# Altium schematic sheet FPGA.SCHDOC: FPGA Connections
size A2; Organization: Altium Limited.; Address1: Level 3, 12a Rodborough Rd; Address2: Frenchs Forest 2086; Address3: NSW; Address4: AUSTRALIA; DocumentNumber: 3; SheetNumber: 4; SheetTotal: 23; PageSetup: Record=PageOptions|CenterHorizontal=True|CenterVertical=True|PrintScale=0.71|XCorrection=1.00|YCorrection=1.00|PrintKind=0|BorderSize=5000000|LeftOffset=0|BottomOffset=0|Orientation=2|PaperLength=4199|PaperWidth=2969|Scale=100|PaperSource=7|PrintQuality=600|MediaType=1|DitherType=10|PaperKind=A3 (297 x 420 mm)|PrintScaleMode=1
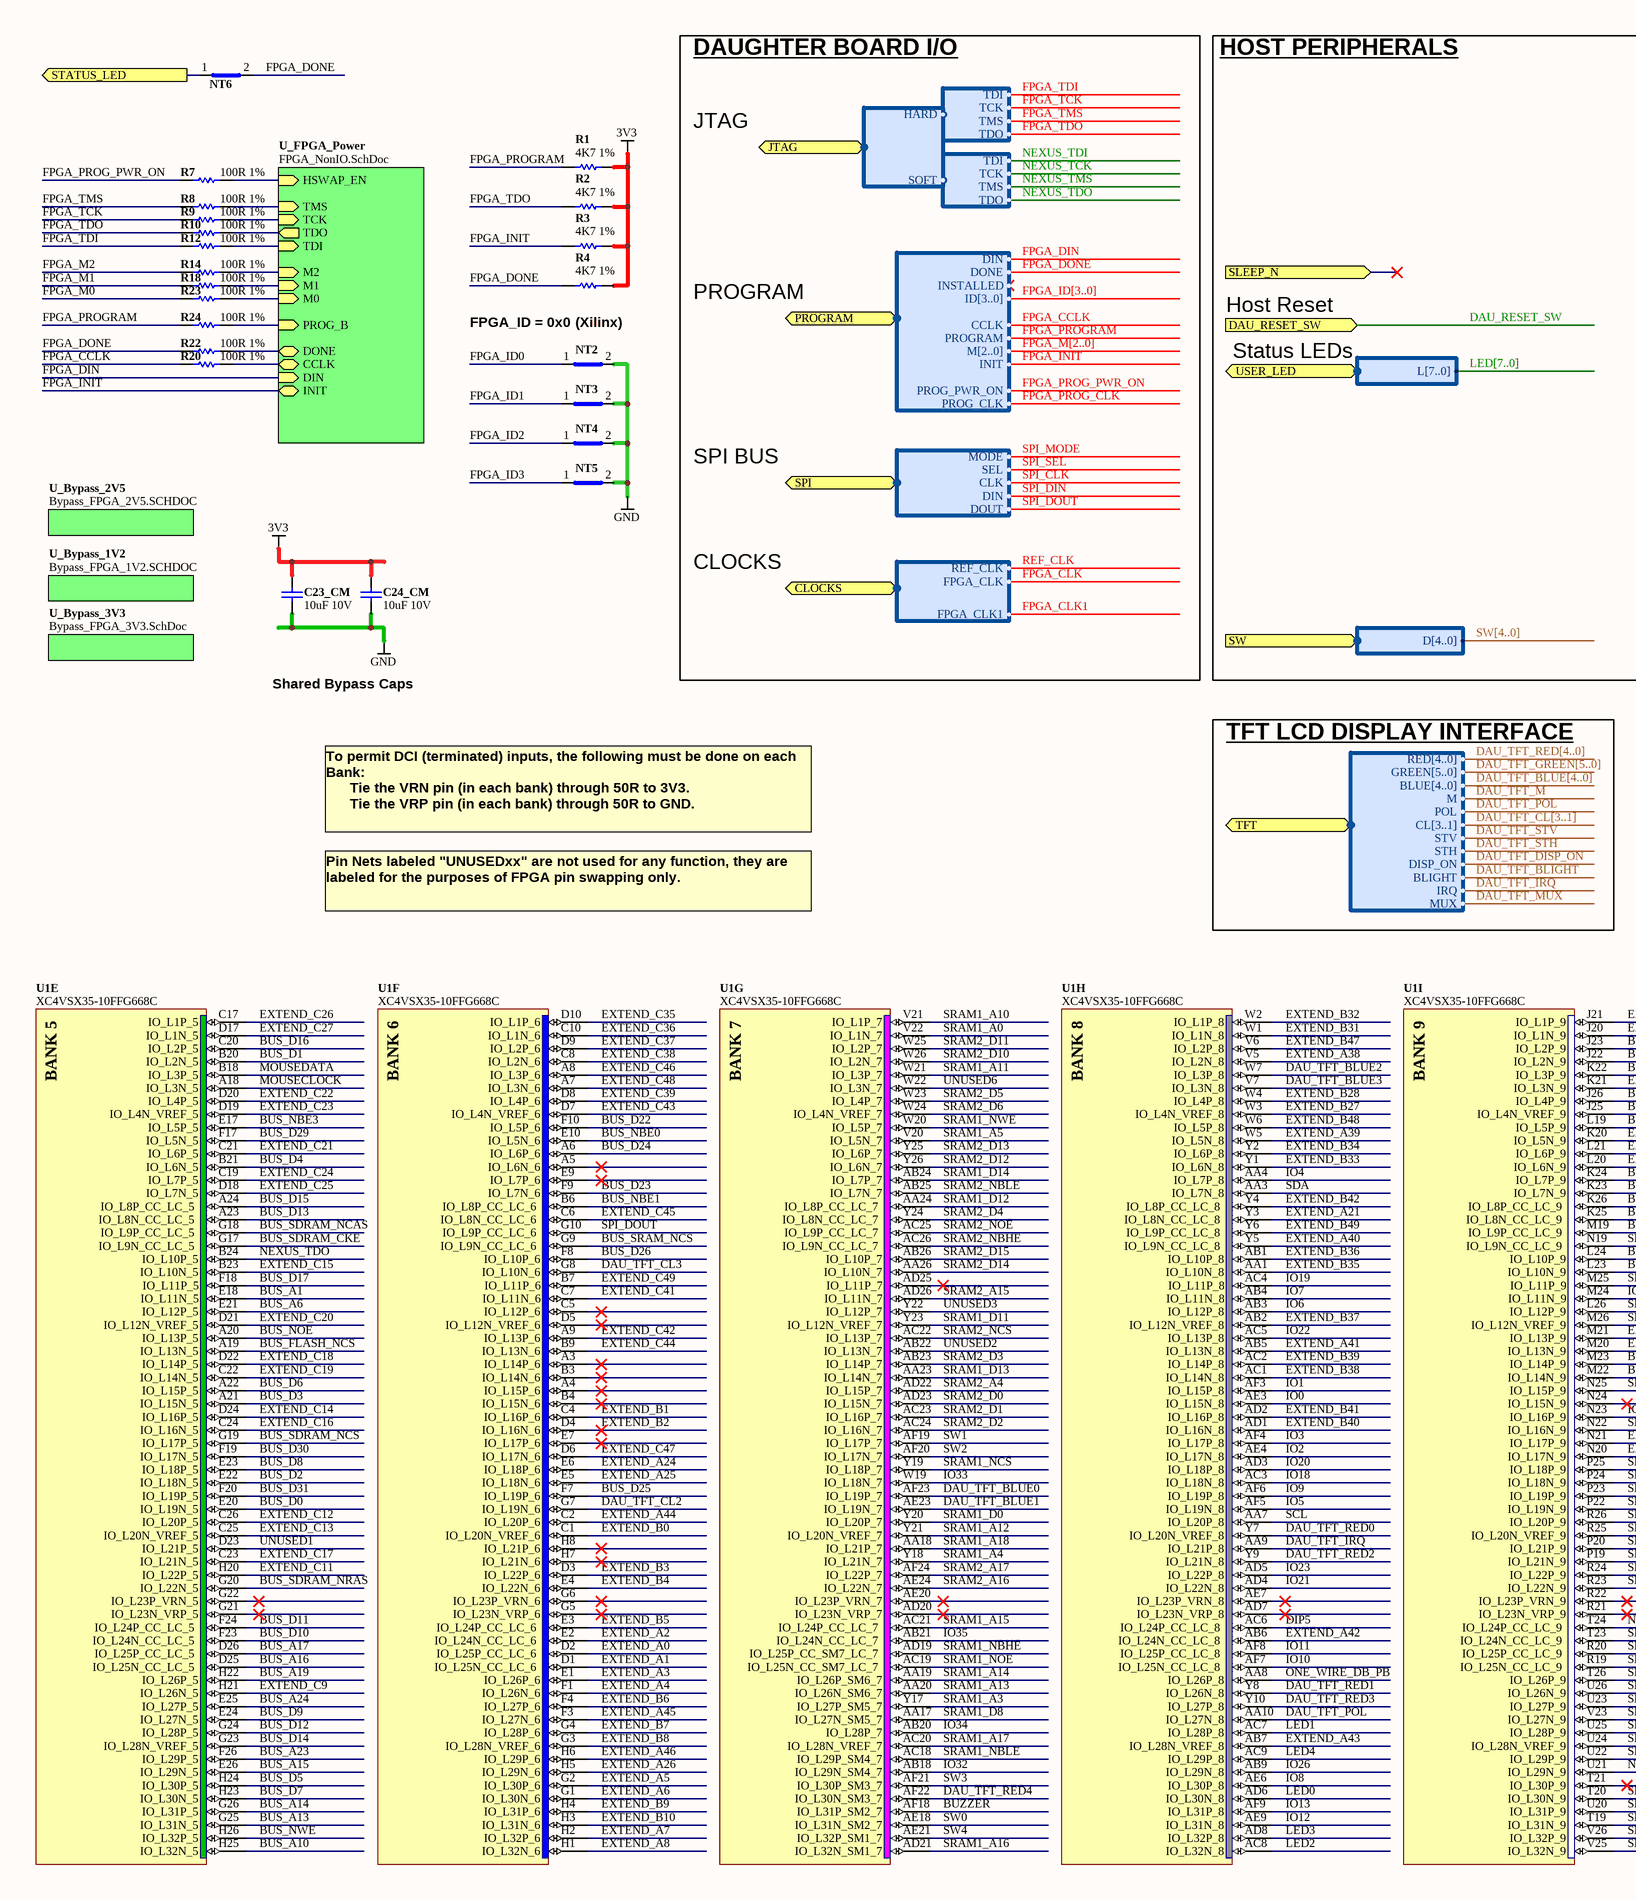
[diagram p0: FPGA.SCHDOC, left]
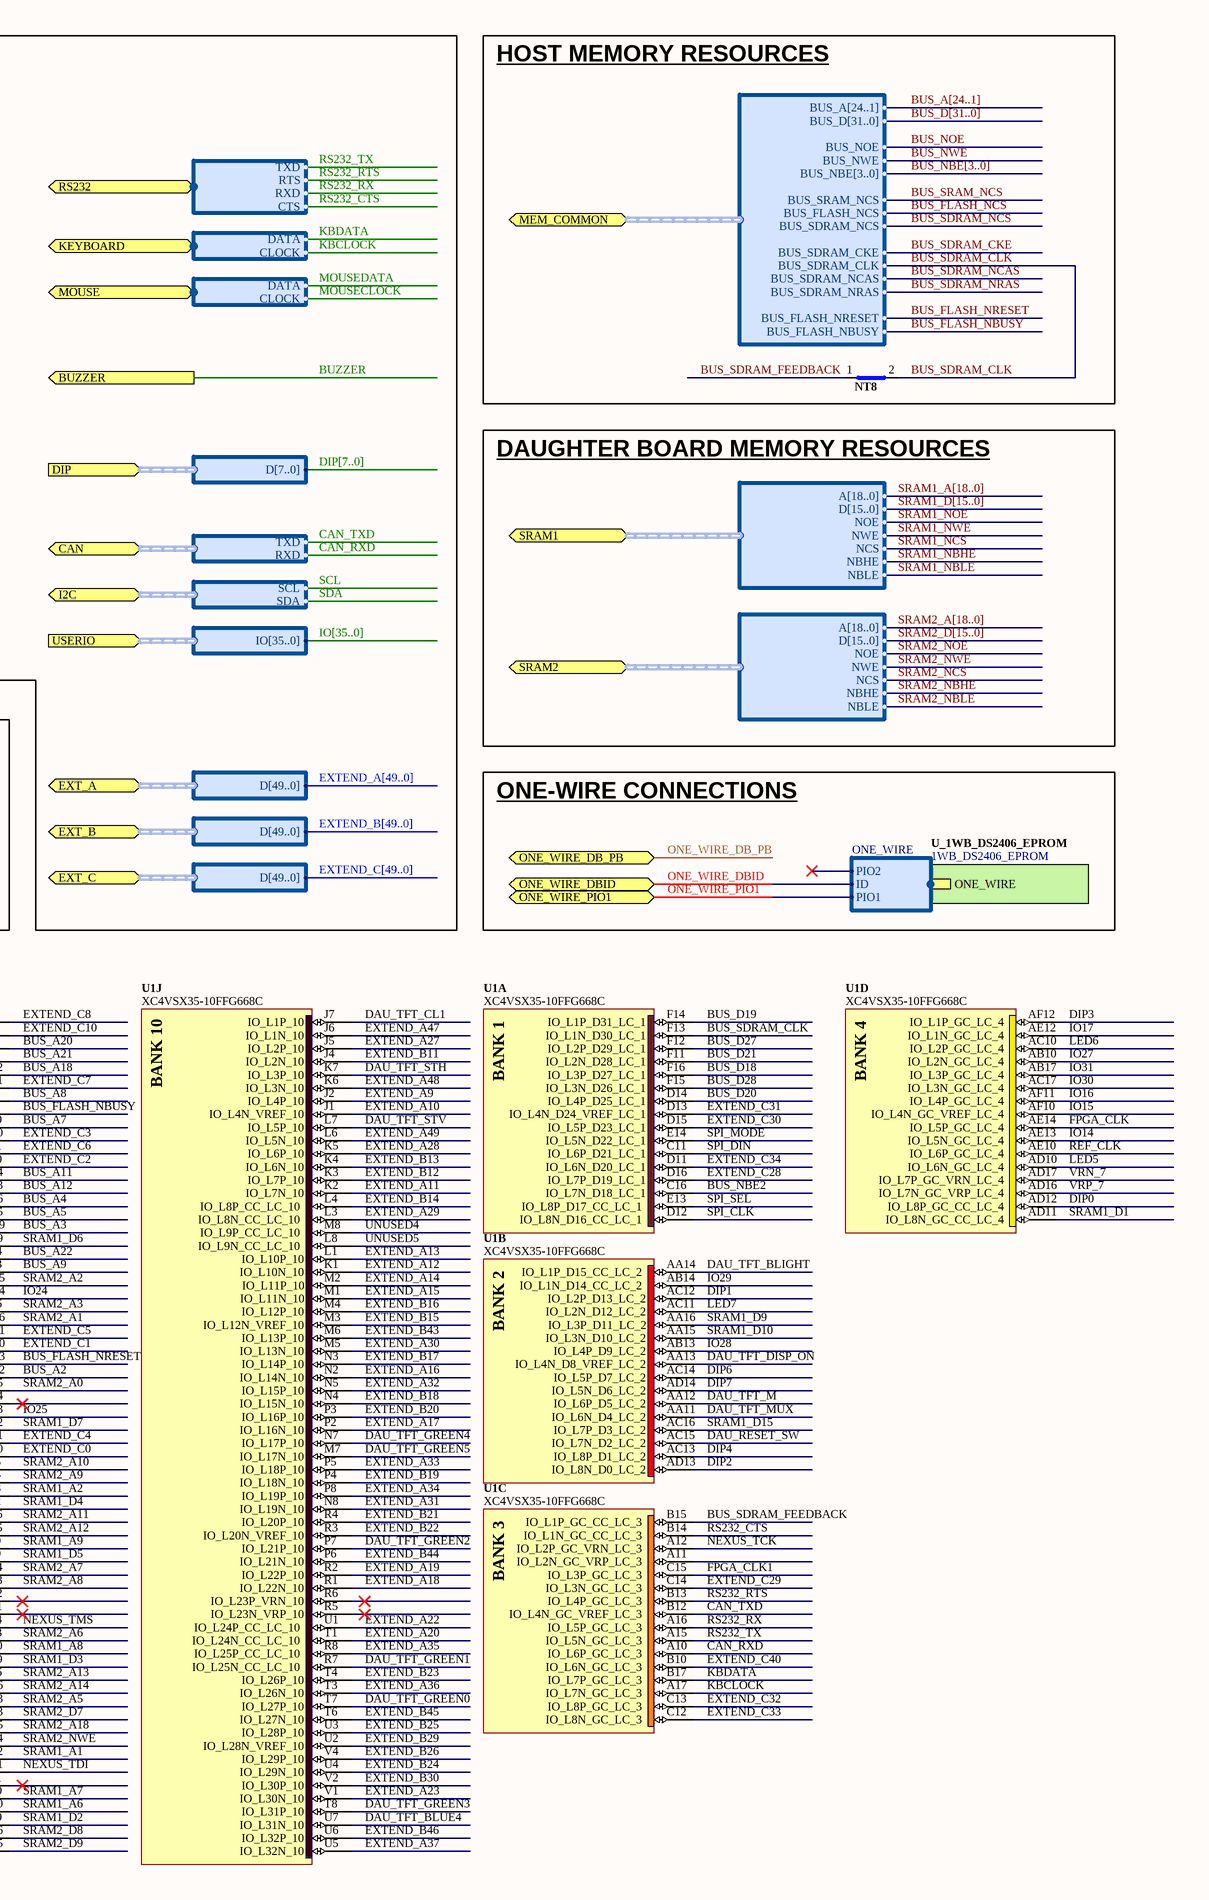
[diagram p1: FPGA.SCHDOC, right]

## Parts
C23_CM  10uF 10V  [CAPC2012-STAR]
C24_CM  10uF 10V  [CAPC2012-STAR]
NT2  Net Tie SMT2  [NETTIE-SMT2-8X8]  (value not drawn)  (net tie, no BOM)
NT3  Net Tie SMT2  [NETTIE-SMT2-8X8]  (value not drawn)  (net tie, no BOM)
NT4  Net Tie SMT2  [NETTIE-SMT2-8X8]  (value not drawn)  (net tie, no BOM)
NT5  Net Tie SMT2  [NETTIE-SMT2-8X8]  (value not drawn)  (net tie, no BOM)
NT6  Net Tie SMT2  [NETTIE-SMT2-8X8]  (value not drawn)  (net tie, no BOM)
NT8  Net Tie SMT2  [NETTIE-SMT2-8X8]  (value not drawn)  (net tie, no BOM)
R1  4K7 1%  [RESC1005-STAR]
R2  4K7 1%  [RESC1005-STAR]
R3  4K7 1%  [RESC1005-STAR]
R4  4K7 1%  [RESC1005-STAR]
R7  100R 1%  [RESC1005-STAR]
R8  100R 1%  [RESC1005-STAR]
R9  100R 1%  [RESC1005-STAR]
R10  100R 1%  [RESC1005-STAR]
R12  100R 1%  [RESC1005-STAR]
R14  100R 1%  [RESC1005-STAR]
R18  100R 1%  [RESC1005-STAR]
R20  100R 1%  [RESC1005-STAR]
R22  100R 1%  [RESC1005-STAR]
R23  100R 1%  [RESC1005-STAR]
R24  100R 1%  [RESC1005-STAR]
U1  XC4VSX35-10FFG668C  [XC4VLX25-10FF668C]  (parts A,B,C,D,E,F,G,H,I,J of 14)

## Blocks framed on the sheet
HOST MEMORY RESOURCES: NT8

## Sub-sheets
U_1WB_DS2406_EPROM = 1WB_DS2406_EPROM: ONE_WIRE (harness ONE_WIRE)
U_Bypass_1V2 = Bypass_FPGA_1V2.SCHDOC: no entries
U_Bypass_2V5 = Bypass_FPGA_2V5.SCHDOC: no entries
U_Bypass_3V3 = Bypass_FPGA_3V3.SchDoc: no entries
U_FPGA_Power = FPGA_NonIO.SchDoc: TMS (in), DONE (bidir), M1 (in), CCLK (bidir), M0 (in), M2 (in), TCK (in), HSWAP_EN (in), TDI (in), PROG_B (in), TDO (out), DIN (in), INIT (bidir)

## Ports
BUZZER (out), CAN (harness CAN_INT), CLOCKS (harness DAU_CLK), DAU_RESET_SW (in), DIP (harness SW8), EXT_A (harness PBIO), EXT_B (harness PBIO), EXT_C (harness PBIO), I2C (harness I2C), JTAG (harness HARDSOFT_JTAG), KEYBOARD (harness PS2), MEM_COMMON (harness HOSTMEMORY), MOUSE (harness PS2), ONE_WIRE_DB_PB (bidir), ONE_WIRE_DBID (bidir), ONE_WIRE_PIO1 (bidir), PROGRAM (harness DAU_CTRL), RS232 (harness RS232_INT), SLEEP_N (in), SPI (harness DAU_SPI), SRAM1 (harness SRAM-256Kx16), SRAM2 (harness SRAM-256Kx16), STATUS_LED (out), SW (harness SW5), TFT (harness DAU_TFT), USER_LED (harness LED8), USERIO (harness IO36)

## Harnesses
ONE_WIRE: ID, PIO1, PIO2
SRAM-256Kx16: A[18..0], D[15..0], NCS, NWE, NOE, NBHE, NBLE
HOSTMEMORY: BUS_A[24..1], BUS_D[31..0], BUS_NOE, BUS_NWE, BUS_NBE[3..0], BUS_SRAM_NCS, BUS_FLASH_NCS, BUS_SDRAM_NCS, BUS_SDRAM_CKE, BUS_SDRAM_CLK, BUS_SDRAM_NCAS, BUS_SDRAM_NRAS, BUS_FLASH_NRESET, BUS_FLASH_NBUSY
DAU_CLK: REF_CLK, FPGA_CLK, FPGA_CLK1
DAU_SPI: MODE, SEL, CLK, DIN, DOUT
DAU_CTRL: DIN, DONE, INSTALLED, ID[3..0], CCLK, PROGRAM, M[2..0], INIT, PROG_PWR_ON, PROG_CLK
JTAG: TMS, TDO, TDI, TCK
HARDSOFT_JTAG: HARD, SOFT
LED8: L[7..0]
SW5: D[4..0]
DAU_TFT: RED[4..0], GREEN[5..0], BLUE[4..0], M, POL, CL[3..1], STV, STH, DISP_ON, BLIGHT, IRQ, MUX
PS2: DATA, CLOCK
RS232_INT: RXD, TXD, RTS, CTS
IO36: IO[35..0]
SW8: D[7..0]
CAN_INT: TXD, RXD
I2C: SCL, SDA
PBIO: D[49..0]

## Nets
3V3: C23_CM.1 C24_CM.1 R1.2 R2.2 R3.2 R4.2
GND: C23_CM.2 C24_CM.2 NT2.2(Net2) NT3.2(Net2) NT4.2(Net2) NT5.2(Net2)
BUS_A1: U1.E18(IO_L11N_5)
BUS_A2: U1.M22(IO_L14N_9)
BUS_A3: U1.M19(IO_L9P_CC_LC_9)
BUS_A4: U1.K26(IO_L8P_CC_LC_9)
BUS_A5: U1.K25(IO_L8N_CC_LC_9)
BUS_A6: U1.E21(IO_L12P_5)
BUS_A7: U1.L19(IO_L5P_9)
BUS_A8: U1.J26(IO_L4P_9)
BUS_A9: U1.L23(IO_L10N_9)
BUS_A10: U1.H25(IO_L32N_5)
BUS_A11: U1.K24(IO_L7P_9)
BUS_A12: U1.K23(IO_L7N_9)
BUS_A13: U1.G25(IO_L31N_5)
BUS_A14: U1.G26(IO_L31P_5)
BUS_A15: U1.E26(IO_L29N_5)
BUS_A16: U1.D25(IO_L25N_CC_LC_5)
BUS_A17: U1.D26(IO_L25P_CC_LC_5)
BUS_A18: U1.K22(IO_L3P_9)
BUS_A19: U1.H22(IO_L26P_5)
BUS_A20: U1.J23(IO_L2P_9)
BUS_A21: U1.J22(IO_L2N_9)
BUS_A22: U1.L24(IO_L10P_9)
BUS_A23: U1.F26(IO_L29P_5)
BUS_A24: U1.E25(IO_L27P_5)
BUS_D0: U1.E20(IO_L19N_5)
BUS_D1: U1.B20(IO_L2N_5)
BUS_D2: U1.E22(IO_L18N_5)
BUS_D3: U1.A21(IO_L15N_5)
BUS_D4: U1.B21(IO_L6N_5)
BUS_D5: U1.H24(IO_L30P_5)
BUS_D6: U1.A22(IO_L15P_5)
BUS_D7: U1.H23(IO_L30N_5)
BUS_D8: U1.E23(IO_L18P_5)
BUS_D9: U1.E24(IO_L27N_5)
BUS_D10: U1.F23(IO_L24N_CC_LC_5)
BUS_D11: U1.F24(IO_L24P_CC_LC_5)
BUS_D12: U1.G24(IO_L28P_5)
BUS_D13: U1.A23(IO_L8N_CC_LC_5)
BUS_D14: U1.G23(IO_L28N_VREF_5)
BUS_D15: U1.A24(IO_L8P_CC_LC_5)
BUS_D16: U1.C20(IO_L2P_5)
BUS_D17: U1.F18(IO_L11P_5)
BUS_D18: U1.F16(IO_L3P_D27_LC_1)
BUS_D19: U1.F14(IO_L1P_D31_LC_1)
BUS_D20: U1.D14(IO_L4P_D25_LC_1)
BUS_D21: U1.F11(IO_L2N_D28_LC_1)
BUS_D22: U1.F10(IO_L5P_6)
BUS_D23: U1.F9(IO_L7N_6)
BUS_D24: U1.A6(IO_L6P_6)
BUS_D25: U1.F7(IO_L19P_6)
BUS_D26: U1.F8(IO_L10P_6)
BUS_D27: U1.F12(IO_L2P_D29_LC_1)
BUS_D28: U1.F15(IO_L3N_D26_LC_1)
BUS_D29: U1.F17(IO_L5N_5)
BUS_D30: U1.F19(IO_L17N_5)
BUS_D31: U1.F20(IO_L19P_5)
BUS_FLASH_NBUSY: U1.J25(IO_L4N_VREF_9) ; port MEM_COMMON.BUS_FLASH_NBUSY
BUS_FLASH_NCS: U1.A19(IO_L13N_5) ; port MEM_COMMON.BUS_FLASH_NCS
BUS_FLASH_NRESET: U1.M23(IO_L14P_9) ; port MEM_COMMON.BUS_FLASH_NRESET
BUS_NBE0: U1.E10(IO_L5N_6)
BUS_NBE1: U1.B6(IO_L8P_CC_LC_6)
BUS_NBE2: U1.C16(IO_L7N_D18_LC_1)
BUS_NBE3: U1.E17(IO_L5P_5)
BUS_NOE: U1.A20(IO_L13P_5) ; port MEM_COMMON.BUS_NOE
BUS_NWE: U1.H26(IO_L32P_5) ; port MEM_COMMON.BUS_NWE
BUS_SDRAM_CKE: U1.G17(IO_L9N_CC_LC_5) ; port MEM_COMMON.BUS_SDRAM_CKE
BUS_SDRAM_CLK: NT8.2(Net2) U1.F13(IO_L1N_D30_LC_1) ; port MEM_COMMON.BUS_SDRAM_CLK
BUS_SDRAM_FEEDBACK: NT8.1(Net1) U1.B15(IO_L1P_GC_CC_LC_3)
BUS_SDRAM_NCAS: U1.G18(IO_L9P_CC_LC_5) ; port MEM_COMMON.BUS_SDRAM_NCAS
BUS_SDRAM_NCS: U1.G19(IO_L17P_5) ; port MEM_COMMON.BUS_SDRAM_NCS
BUS_SDRAM_NRAS: U1.G20(IO_L22N_5) ; port MEM_COMMON.BUS_SDRAM_NRAS
BUS_SRAM_NCS: U1.G9(IO_L9N_CC_LC_6) ; port MEM_COMMON.BUS_SRAM_NCS
BUZZER: U1.AF18(IO_L31P_SM2_7) ; port BUZZER
CAN_RXD: U1.A10(IO_L6P_GC_LC_3) ; port CAN.RXD
CAN_TXD: U1.B12(IO_L4N_GC_VREF_LC_3) ; port CAN.TXD
DAU_RESET_SW: U1.AC15(IO_L7N_D2_LC_2) ; port DAU_RESET_SW
DAU_TFT_BLIGHT: U1.AA14(IO_L1P_D15_CC_LC_2) ; port TFT.BLIGHT
DAU_TFT_BLUE0: U1.AF23(IO_L19P_7)
DAU_TFT_BLUE1: U1.AE23(IO_L19N_7)
DAU_TFT_BLUE2: U1.W7(IO_L3P_8)
DAU_TFT_BLUE3: U1.V7(IO_L3N_8)
DAU_TFT_BLUE4: U1.U7(IO_L31N_10)
DAU_TFT_CL1: U1.J7(IO_L1P_10)
DAU_TFT_CL2: U1.G7(IO_L19N_6)
DAU_TFT_CL3: U1.G8(IO_L10N_6)
DAU_TFT_DISP_ON: U1.AA13(IO_L4N_D8_VREF_LC_2) ; port TFT.DISP_ON
DAU_TFT_GREEN0: U1.T7(IO_L27P_10)
DAU_TFT_GREEN1: U1.R7(IO_L25N_CC_LC_10)
DAU_TFT_GREEN2: U1.P7(IO_L21P_10)
DAU_TFT_GREEN3: U1.T8(IO_L31P_10)
DAU_TFT_GREEN4: U1.N7(IO_L17P_10)
DAU_TFT_GREEN5: U1.M7(IO_L17N_10)
DAU_TFT_IRQ: U1.AA9(IO_L21P_8) ; port TFT.IRQ
DAU_TFT_M: U1.AA12(IO_L6P_D5_LC_2) ; port TFT.M
DAU_TFT_MUX: U1.AA11(IO_L6N_D4_LC_2) ; port TFT.MUX
DAU_TFT_POL: U1.AA10(IO_L27N_8) ; port TFT.POL
DAU_TFT_RED0: U1.Y7(IO_L20N_VREF_8)
DAU_TFT_RED1: U1.Y8(IO_L26N_8)
DAU_TFT_RED2: U1.Y9(IO_L21N_8)
DAU_TFT_RED3: U1.Y10(IO_L27P_8)
DAU_TFT_RED4: U1.AF22(IO_L30N_SM3_7)
DAU_TFT_STH: U1.K7(IO_L3P_10) ; port TFT.STH
DAU_TFT_STV: U1.L7(IO_L5P_10) ; port TFT.STV
DIP0: U1.AD12(IO_L8P_GC_CC_LC_4)
DIP1: U1.AC12(IO_L2P_D13_LC_2)
DIP2: U1.AD13(IO_L8N_D0_LC_2)
DIP3: U1.AF12(IO_L1P_GC_LC_4)
DIP4: U1.AC13(IO_L8P_D1_LC_2)
DIP5: U1.AC6(IO_L24P_CC_LC_8)
DIP6: U1.AC14(IO_L5P_D7_LC_2)
DIP7: U1.AD14(IO_L5N_D6_LC_2)
EXTEND_A0: U1.D2(IO_L25P_CC_LC_6)
EXTEND_A1: U1.D1(IO_L25N_CC_LC_6)
EXTEND_A2: U1.E2(IO_L24N_CC_LC_6)
EXTEND_A3: U1.E1(IO_L26P_6)
EXTEND_A4: U1.F1(IO_L26N_6)
EXTEND_A5: U1.G2(IO_L30P_6)
EXTEND_A6: U1.G1(IO_L30N_6)
EXTEND_A7: U1.H2(IO_L32P_6)
EXTEND_A8: U1.H1(IO_L32N_6)
EXTEND_A9: U1.J2(IO_L4P_10)
EXTEND_A10: U1.J1(IO_L4N_VREF_10)
EXTEND_A11: U1.K2(IO_L7N_10)
EXTEND_A12: U1.K1(IO_L10N_10)
EXTEND_A13: U1.L1(IO_L10P_10)
EXTEND_A14: U1.M2(IO_L11P_10)
EXTEND_A15: U1.M1(IO_L11N_10)
EXTEND_A16: U1.N2(IO_L14N_10)
EXTEND_A17: U1.P2(IO_L16N_10)
EXTEND_A18: U1.R1(IO_L22N_10)
EXTEND_A19: U1.R2(IO_L22P_10)
EXTEND_A20: U1.T1(IO_L24N_CC_LC_10)
EXTEND_A21: U1.Y3(IO_L8N_CC_LC_8)
EXTEND_A22: U1.U1(IO_L24P_CC_LC_10)
EXTEND_A23: U1.V1(IO_L30N_10)
EXTEND_A24: U1.E6(IO_L18P_6)
EXTEND_A25: U1.E5(IO_L18N_6)
EXTEND_A26: U1.H5(IO_L29N_6)
EXTEND_A27: U1.J5(IO_L2P_10)
EXTEND_A28: U1.K5(IO_L6P_10)
EXTEND_A29: U1.L3(IO_L8N_CC_LC_10)
EXTEND_A30: U1.M5(IO_L13N_10)
EXTEND_A31: U1.N8(IO_L19N_10)
EXTEND_A32: U1.N5(IO_L15P_10)
EXTEND_A33: U1.P5(IO_L18P_10)
EXTEND_A34: U1.P8(IO_L19P_10)
EXTEND_A35: U1.R8(IO_L25P_CC_LC_10)
EXTEND_A36: U1.T3(IO_L26N_10)
EXTEND_A37: U1.U5(IO_L32N_10)
EXTEND_A38: U1.V5(IO_L2N_8)
EXTEND_A39: U1.W5(IO_L5N_8)
EXTEND_A40: U1.Y5(IO_L9N_CC_LC_8)
EXTEND_A41: U1.AB5(IO_L13N_8)
EXTEND_A42: U1.AB6(IO_L24N_CC_LC_8)
EXTEND_A43: U1.AB7(IO_L28N_VREF_8)
EXTEND_A44: U1.C2(IO_L20P_6)
EXTEND_A45: U1.F3(IO_L27N_6)
EXTEND_A46: U1.H6(IO_L29P_6)
EXTEND_A47: U1.J6(IO_L1N_10)
EXTEND_A48: U1.K6(IO_L3N_10)
EXTEND_A49: U1.L6(IO_L5N_10)
EXTEND_B0: U1.C1(IO_L20N_VREF_6)
EXTEND_B1: U1.C4(IO_L16P_6)
EXTEND_B2: U1.D4(IO_L16N_6)
EXTEND_B3: U1.D3(IO_L22P_6)
EXTEND_B4: U1.E4(IO_L22N_6)
EXTEND_B5: U1.E3(IO_L24P_CC_LC_6)
EXTEND_B6: U1.F4(IO_L27P_6)
EXTEND_B7: U1.G4(IO_L28P_6)
EXTEND_B8: U1.G3(IO_L28N_VREF_6)
EXTEND_B9: U1.H4(IO_L31P_6)
EXTEND_B10: U1.H3(IO_L31N_6)
EXTEND_B11: U1.J4(IO_L2N_10)
EXTEND_B12: U1.K3(IO_L7P_10)
EXTEND_B13: U1.K4(IO_L6N_10)
EXTEND_B14: U1.L4(IO_L8P_CC_LC_10)
EXTEND_B15: U1.M3(IO_L12N_VREF_10)
EXTEND_B16: U1.M4(IO_L12P_10)
EXTEND_B17: U1.N3(IO_L14P_10)
EXTEND_B18: U1.N4(IO_L15N_10)
EXTEND_B19: U1.P4(IO_L18N_10)
EXTEND_B20: U1.P3(IO_L16P_10)
EXTEND_B21: U1.R4(IO_L20P_10)
EXTEND_B22: U1.R3(IO_L20N_VREF_10)
EXTEND_B23: U1.T4(IO_L26P_10)
EXTEND_B24: U1.U4(IO_L29N_10)
EXTEND_B25: U1.U3(IO_L28P_10)
EXTEND_B26: U1.V4(IO_L29P_10)
EXTEND_B27: U1.W3(IO_L4N_VREF_8)
EXTEND_B28: U1.W4(IO_L4P_8)
EXTEND_B29: U1.U2(IO_L28N_VREF_10)
EXTEND_B30: U1.V2(IO_L30P_10)
EXTEND_B31: U1.W1(IO_L1N_8)
EXTEND_B32: U1.W2(IO_L1P_8)
EXTEND_B33: U1.Y1(IO_L6N_8)
EXTEND_B34: U1.Y2(IO_L6P_8)
EXTEND_B35: U1.AA1(IO_L10N_8)
EXTEND_B36: U1.AB1(IO_L10P_8)
EXTEND_B37: U1.AB2(IO_L12N_VREF_8)
EXTEND_B38: U1.AC1(IO_L14N_8)
EXTEND_B39: U1.AC2(IO_L14P_8)
EXTEND_B40: U1.AD1(IO_L16N_8)
EXTEND_B41: U1.AD2(IO_L16P_8)
EXTEND_B42: U1.Y4(IO_L8P_CC_LC_8)
EXTEND_B43: U1.M6(IO_L13P_10)
EXTEND_B44: U1.P6(IO_L21N_10)
EXTEND_B45: U1.T6(IO_L27N_10)
EXTEND_B46: U1.U6(IO_L32P_10)
EXTEND_B47: U1.V6(IO_L2P_8)
EXTEND_B48: U1.W6(IO_L5P_8)
EXTEND_B49: U1.Y6(IO_L9P_CC_LC_8)
EXTEND_C0: U1.N20(IO_L17N_9)
EXTEND_C1: U1.M20(IO_L13N_9)
EXTEND_C2: U1.L20(IO_L6N_9)
EXTEND_C3: U1.K20(IO_L5N_9)
EXTEND_C4: U1.N21(IO_L17P_9)
EXTEND_C5: U1.M21(IO_L13P_9)
EXTEND_C6: U1.L21(IO_L6P_9)
EXTEND_C7: U1.K21(IO_L3N_9)
EXTEND_C8: U1.J21(IO_L1P_9)
EXTEND_C9: U1.H21(IO_L26N_5)
EXTEND_C10: U1.J20(IO_L1N_9)
EXTEND_C11: U1.H20(IO_L22P_5)
EXTEND_C12: U1.C26(IO_L20P_5)
EXTEND_C13: U1.C25(IO_L20N_VREF_5)
EXTEND_C14: U1.D24(IO_L16P_5)
EXTEND_C15: U1.B23(IO_L10N_5)
EXTEND_C16: U1.C24(IO_L16N_5)
EXTEND_C17: U1.C23(IO_L21N_5)
EXTEND_C18: U1.D22(IO_L14P_5)
EXTEND_C19: U1.C22(IO_L14N_5)
EXTEND_C20: U1.D21(IO_L12N_VREF_5)
EXTEND_C21: U1.C21(IO_L6P_5)
EXTEND_C22: U1.D20(IO_L4P_5)
EXTEND_C23: U1.D19(IO_L4N_VREF_5)
EXTEND_C24: U1.C19(IO_L7P_5)
EXTEND_C25: U1.D18(IO_L7N_5)
EXTEND_C26: U1.C17(IO_L1P_5)
EXTEND_C27: U1.D17(IO_L1N_5)
EXTEND_C28: U1.D16(IO_L7P_D19_LC_1)
EXTEND_C29: U1.C14(IO_L3N_GC_LC_3)
EXTEND_C30: U1.D15(IO_L5P_D23_LC_1)
EXTEND_C31: U1.D13(IO_L4N_D24_VREF_LC_1)
EXTEND_C32: U1.C13(IO_L8P_GC_LC_3)
EXTEND_C33: U1.C12(IO_L8N_GC_LC_3)
EXTEND_C34: U1.D11(IO_L6N_D20_LC_1)
EXTEND_C35: U1.D10(IO_L1P_6)
EXTEND_C36: U1.C10(IO_L1N_6)
EXTEND_C37: U1.D9(IO_L2P_6)
EXTEND_C38: U1.C8(IO_L2N_6)
EXTEND_C39: U1.D8(IO_L4P_6)
EXTEND_C40: U1.B10(IO_L6N_GC_LC_3)
EXTEND_C41: U1.C7(IO_L11N_6)
EXTEND_C42: U1.A9(IO_L13P_6)
EXTEND_C43: U1.D7(IO_L4N_VREF_6)
EXTEND_C44: U1.B9(IO_L13N_6)
EXTEND_C45: U1.C6(IO_L8N_CC_LC_6)
EXTEND_C46: U1.A8(IO_L3P_6)
EXTEND_C47: U1.D6(IO_L17N_6)
EXTEND_C48: U1.A7(IO_L3N_6)
EXTEND_C49: U1.B7(IO_L11P_6)
FPGA_CCLK: R20.1 ; port PROGRAM.CCLK
FPGA_CLK: U1.AE14(IO_L5P_GC_LC_4) ; port CLOCKS.FPGA_CLK
FPGA_CLK1: U1.C15(IO_L3P_GC_LC_3) ; port CLOCKS.FPGA_CLK1
FPGA_DIN: sheet U_FPGA_Power/DIN, port PROGRAM.DIN
FPGA_DONE: NT6.2(Net2) R4.1 R22.1 ; port PROGRAM.DONE
FPGA_ID0: NT2.1(Net1)
FPGA_ID1: NT3.1(Net1)
FPGA_ID2: NT4.1(Net1)
FPGA_ID3: NT5.1(Net1)
FPGA_INIT: R3.1 ; sheet U_FPGA_Power/INIT, port PROGRAM.INIT
FPGA_M0: R23.1
FPGA_M1: R18.1
FPGA_M2: R14.1
FPGA_PROG_PWR_ON: R7.1 ; port PROGRAM.PROG_PWR_ON
FPGA_PROGRAM: R1.1 R24.1 ; port PROGRAM.PROGRAM
FPGA_TCK: R9.1 ; harness JTAG.TCK
FPGA_TDI: R12.1 ; harness JTAG.TDI
FPGA_TDO: R2.1 R10.1 ; harness JTAG.TDO
FPGA_TMS: R8.1 ; harness JTAG.TMS
IO0: U1.AE3(IO_L15N_8)
IO1: U1.AF3(IO_L15P_8)
IO2: U1.AE4(IO_L17N_8)
IO3: U1.AF4(IO_L17P_8)
IO4: U1.AA4(IO_L7P_8)
IO5: U1.AF5(IO_L19N_8)
IO6: U1.AB3(IO_L12P_8)
IO7: U1.AB4(IO_L11N_8)
IO8: U1.AE6(IO_L30P_8)
IO9: U1.AF6(IO_L19P_8)
IO10: U1.AF7(IO_L25N_CC_LC_8)
IO11: U1.AF8(IO_L25P_CC_LC_8)
IO12: U1.AE9(IO_L31N_8)
IO13: U1.AF9(IO_L31P_8)
IO14: U1.AE13(IO_L5N_GC_LC_4)
IO15: U1.AF10(IO_L4N_GC_VREF_LC_4)
IO16: U1.AF11(IO_L4P_GC_LC_4)
IO17: U1.AE12(IO_L1N_GC_LC_4)
IO18: U1.AC3(IO_L18N_8)
IO19: U1.AC4(IO_L11P_8)
IO20: U1.AD3(IO_L18P_8)
IO21: U1.AD4(IO_L22N_8)
IO22: U1.AC5(IO_L13P_8)
IO23: U1.AD5(IO_L22P_8)
IO24: U1.M24(IO_L11N_9)
IO25: U1.N23(IO_L16P_9)
IO26: U1.AB9(IO_L29N_8)
IO27: U1.AB10(IO_L2N_GC_LC_4)
IO28: U1.AB13(IO_L4P_D9_LC_2)
IO29: U1.AB14(IO_L1N_D14_CC_LC_2)
IO30: U1.AC17(IO_L3N_GC_LC_4)
IO31: U1.AB17(IO_L3P_GC_LC_4)
IO32: U1.AB18(IO_L29N_SM4_7)
IO33: U1.W19(IO_L18N_7)
IO34: U1.AB20(IO_L28P_7)
IO35: U1.AB21(IO_L24N_CC_LC_7)
KBCLOCK: U1.A17(IO_L7N_GC_LC_3) ; port KEYBOARD.CLOCK
KBDATA: U1.B17(IO_L7P_GC_LC_3) ; port KEYBOARD.DATA
LED0: U1.AD6(IO_L30N_8)
LED1: U1.AC7(IO_L28P_8)
LED2: U1.AC8(IO_L32N_8)
LED3: U1.AD8(IO_L32P_8)
LED4: U1.AC9(IO_L29P_8)
LED5: U1.AD10(IO_L6N_GC_LC_4)
LED6: U1.AC10(IO_L2P_GC_LC_4)
LED7: U1.AC11(IO_L2N_D12_LC_2)
MOUSECLOCK: U1.A18(IO_L3N_5) ; port MOUSE.CLOCK
MOUSEDATA: U1.B18(IO_L3P_5) ; port MOUSE.DATA
NEXUS_TCK: U1.A12(IO_L2P_GC_VRN_LC_3) ; harness JTAG.TCK
NEXUS_TDI: U1.U21(IO_L29N_9) ; harness JTAG.TDI
NEXUS_TDO: U1.B24(IO_L10P_5) ; harness JTAG.TDO
NEXUS_TMS: U1.T24(IO_L24P_CC_LC_9) ; harness JTAG.TMS
ONE_WIRE_DB_PB: U1.AA8(IO_L26P_8) ; port ONE_WIRE_DB_PB
ONE_WIRE_DBID: port ONE_WIRE_DBID, sheet U_1WB_DS2406_EPROM/ONE_WIRE.ID
ONE_WIRE_PIO1: port ONE_WIRE_PIO1, sheet U_1WB_DS2406_EPROM/ONE_WIRE.PIO1
REF_CLK: U1.AE10(IO_L6P_GC_LC_4) ; port CLOCKS.REF_CLK
RS232_CTS: U1.B14(IO_L1N_GC_CC_LC_3) ; port RS232.CTS
RS232_RTS: U1.B13(IO_L4P_GC_LC_3) ; port RS232.RTS
RS232_RX: U1.A16(IO_L5P_GC_LC_3) ; port RS232.RXD
RS232_TX: U1.A15(IO_L5N_GC_LC_3) ; port RS232.TXD
SCL: U1.AA7(IO_L20P_8) ; port I2C.SCL
SDA: U1.AA3(IO_L7N_8) ; port I2C.SDA
SPI_CLK: U1.D12(IO_L8N_D16_CC_LC_1) ; port SPI.CLK
SPI_DIN: U1.C11(IO_L6P_D21_LC_1) ; port SPI.DIN
SPI_DOUT: U1.G10(IO_L9P_CC_LC_6) ; port SPI.DOUT
SPI_MODE: U1.E14(IO_L5N_D22_LC_1) ; port SPI.MODE
SPI_SEL: U1.E13(IO_L8P_D17_CC_LC_1) ; port SPI.SEL
SRAM1_A0: U1.V22(IO_L1N_7)
SRAM1_A1: U1.U22(IO_L29P_9)
SRAM1_A2: U1.P23(IO_L19P_9)
SRAM1_A3: U1.Y17(IO_L27P_SM5_7)
SRAM1_A4: U1.Y18(IO_L21N_7)
SRAM1_A5: U1.V20(IO_L5N_7)
SRAM1_A6: U1.U20(IO_L31P_9)
SRAM1_A7: U1.T20(IO_L30N_9)
SRAM1_A8: U1.R20(IO_L25P_CC_LC_9)
SRAM1_A9: U1.P20(IO_L21P_9)
SRAM1_A10: U1.V21(IO_L1P_7)
SRAM1_A11: U1.W21(IO_L3P_7)
SRAM1_A12: U1.Y21(IO_L20N_VREF_7)
SRAM1_A13: U1.AA20(IO_L26N_SM6_7)
SRAM1_A14: U1.AA19(IO_L26P_SM6_7)
SRAM1_A15: U1.AC21(IO_L24P_CC_LC_7)
SRAM1_A16: U1.AD21(IO_L32N_SM1_7)
SRAM1_A17: U1.AC20(IO_L28N_VREF_7)
SRAM1_A18: U1.AA18(IO_L21P_7)
SRAM1_D0: U1.Y20(IO_L20P_7)
SRAM1_D1: U1.AD11(IO_L8N_GC_CC_LC_4)
SRAM1_D2: U1.T19(IO_L31N_9)
SRAM1_D3: U1.R19(IO_L25N_CC_LC_9)
SRAM1_D4: U1.P22(IO_L19N_9)
SRAM1_D5: U1.P19(IO_L21N_9)
SRAM1_D6: U1.N19(IO_L9N_CC_LC_9)
SRAM1_D7: U1.N22(IO_L16N_9)
SRAM1_D8: U1.AA17(IO_L27N_SM5_7)
SRAM1_D9: U1.AA16(IO_L3P_D11_LC_2)
SRAM1_D10: U1.AA15(IO_L3N_D10_LC_2)
SRAM1_D11: U1.Y23(IO_L12N_VREF_7)
SRAM1_D12: U1.AA24(IO_L8P_CC_LC_7)
SRAM1_D13: U1.AA23(IO_L14N_7)
SRAM1_D14: U1.AB24(IO_L7P_7)
SRAM1_D15: U1.AC16(IO_L7P_D3_LC_2)
SRAM1_NBHE: U1.AD19(IO_L25P_CC_SM7_LC_7) ; port SRAM1.NBHE
SRAM1_NBLE: U1.AC18(IO_L29P_SM4_7) ; port SRAM1.NBLE
SRAM1_NCS: U1.Y19(IO_L18P_7) ; port SRAM1.NCS
SRAM1_NOE: U1.AC19(IO_L25N_CC_SM7_LC_7) ; port SRAM1.NOE
SRAM1_NWE: U1.W20(IO_L5P_7) ; port SRAM1.NWE
SRAM2_A0: U1.N25(IO_L15P_9)
SRAM2_A1: U1.M26(IO_L12N_VREF_9)
SRAM2_A2: U1.M25(IO_L11P_9)
SRAM2_A3: U1.L26(IO_L12P_9)
SRAM2_A4: U1.AD22(IO_L15P_7)
SRAM2_A5: U1.U23(IO_L27P_9)
SRAM2_A6: U1.T23(IO_L24N_CC_LC_9)
SRAM2_A7: U1.R24(IO_L22P_9)
SRAM2_A8: U1.R23(IO_L22N_9)
SRAM2_A9: U1.P24(IO_L18N_9)
SRAM2_A10: U1.P25(IO_L18P_9)
SRAM2_A11: U1.R26(IO_L20P_9)
SRAM2_A12: U1.R25(IO_L20N_VREF_9)
SRAM2_A13: U1.T26(IO_L26P_9)
SRAM2_A14: U1.U26(IO_L26N_9)
SRAM2_A15: U1.AD26(IO_L11N_7)
SRAM2_A16: U1.AE24(IO_L22N_7)
SRAM2_A17: U1.AF24(IO_L22P_7)
SRAM2_A18: U1.U25(IO_L28P_9)
SRAM2_D0: U1.AD23(IO_L15N_7)
SRAM2_D1: U1.AC23(IO_L16P_7)
SRAM2_D2: U1.AC24(IO_L16N_7)
SRAM2_D3: U1.AB23(IO_L14P_7)
SRAM2_D4: U1.Y24(IO_L8N_CC_LC_7)
SRAM2_D5: U1.W23(IO_L4P_7)
SRAM2_D6: U1.W24(IO_L4N_VREF_7)
SRAM2_D7: U1.V23(IO_L27N_9)
SRAM2_D8: U1.V26(IO_L32P_9)
SRAM2_D9: U1.V25(IO_L32N_9)
SRAM2_D10: U1.W26(IO_L2N_7)
SRAM2_D11: U1.W25(IO_L2P_7)
SRAM2_D12: U1.Y26(IO_L6N_7)
SRAM2_D13: U1.Y25(IO_L6P_7)
SRAM2_D14: U1.AA26(IO_L10N_7)
SRAM2_D15: U1.AB26(IO_L10P_7)
SRAM2_NBHE: U1.AC26(IO_L9N_CC_LC_7) ; port SRAM2.NBHE
SRAM2_NBLE: U1.AB25(IO_L7N_7) ; port SRAM2.NBLE
SRAM2_NCS: U1.AC22(IO_L13P_7) ; port SRAM2.NCS
SRAM2_NOE: U1.AC25(IO_L9P_CC_LC_7) ; port SRAM2.NOE
SRAM2_NWE: U1.U24(IO_L28N_VREF_9) ; port SRAM2.NWE
STATUS_LED: NT6.1(Net1) ; port STATUS_LED
SW0: U1.AE18(IO_L31N_SM2_7)
SW1: U1.AF19(IO_L17P_7)
SW2: U1.AF20(IO_L17N_7)
SW3: U1.AF21(IO_L30P_SM3_7)
SW4: U1.AE21(IO_L32P_SM1_7)
UNUSED1: U1.D23(IO_L21P_5)
UNUSED2: U1.AB22(IO_L13N_7)
UNUSED3: U1.Y22(IO_L12P_7)
UNUSED4: U1.M8(IO_L9P_CC_LC_10)
UNUSED5: U1.L8(IO_L9N_CC_LC_10)
UNUSED6: U1.W22(IO_L3N_7)
VRN_7: U1.AD17(IO_L7P_GC_VRN_LC_4)
VRP_7: U1.AD16(IO_L7N_GC_VRP_LC_4)
NetR7_2: R7.2 ; sheet U_FPGA_Power/HSWAP_EN
NetR8_2: R8.2 ; sheet U_FPGA_Power/TMS
NetR9_2: R9.2 ; sheet U_FPGA_Power/TCK
NetR10_2: R10.2 ; sheet U_FPGA_Power/TDO
NetR12_2: R12.2 ; sheet U_FPGA_Power/TDI
NetR14_2: R14.2 ; sheet U_FPGA_Power/M2
NetR18_2: R18.2 ; sheet U_FPGA_Power/M1
NetR20_2: R20.2 ; sheet U_FPGA_Power/CCLK
NetR22_2: R22.2 ; sheet U_FPGA_Power/DONE
NetR23_2: R23.2 ; sheet U_FPGA_Power/M0
NetR24_2: R24.2 ; sheet U_FPGA_Power/PROG_B

Not connected (* = marked no-connect by the designer): U1 A3(IO_L14P_6)* A4(IO_L15P_6)* A5(IO_L6N_6)* A11(IO_L2N_GC_VRP_LC_3) AD7(IO_L23N_VRP_8)* AD20(IO_L23N_VRP_7)* AD25(IO_L11P_7)* AE7(IO_L23P_VRN_8)* AE20(IO_L23P_VRN_7)* B3(IO_L14N_6)* B4(IO_L15N_6)* C5(IO_L12P_6)* D5(IO_L12N_VREF_6)* E7(IO_L17P_6)* E9(IO_L7P_6)* G5(IO_L23N_VRP_6)* G6(IO_L23P_VRN_6)* G21(IO_L23N_VRP_5)* G22(IO_L23P_VRN_5)* H7(IO_L21N_6)* H8(IO_L21P_6)* N24(IO_L15N_9)* R5(IO_L23N_VRP_10)* R6(IO_L23P_VRN_10)* R21(IO_L23N_VRP_9)* R22(IO_L23P_VRN_9)* T21(IO_L30P_9)*

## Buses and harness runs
bus BUS_A[24..1]
bus BUS_D[31..0]
bus BUS_NBE[3..0]
bus DAU_TFT_BLUE[4..0]
bus DAU_TFT_CL[3..1]
bus DAU_TFT_GREEN[5..0]
bus DAU_TFT_RED[4..0]
bus DIP[7..0]
bus EXTEND_A[49..0]
bus EXTEND_B[49..0]
bus EXTEND_C[49..0]
bus FPGA_ID[3..0]
bus FPGA_M[2..0]
bus IO[35..0]
bus LED[7..0]
bus SRAM1_A[18..0]
bus SRAM1_D[15..0]
bus SRAM2_A[18..0]
bus SRAM2_D[15..0]
bus SW[4..0]

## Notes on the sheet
- DAUGHTER BOARD I/O
- HOST PERIPHERALS
- JTAG
- FPGA_ID = 0x0
- (Xilinx)
- PROGRAM
- Host Reset
- Status LEDs
- SPI BUS
- DAUGHTER BOARD MEMORY RESOURCES
- CLOCKS
- Shared Bypass Caps
- TFT LCD DISPLAY INTERFACE
- ONE-WIRE CONNECTIONS
- To permit DCI (terminated) inputs, the following must be done on each Bank:
  Tie the VRN pin (in each bank) through 50R to 3V3.
  Tie the VRP pin (in each bank) through 50R to GND.
- Pin Nets labeled "UNUSEDxx" are not used for any function, they are labeled for the purposes of FPGA pin swapping only.

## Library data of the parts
C23_CM C24_CM = D-101-0087: Capacitor, Ceramic, 10uF 10% 10V 0805 (2012) X5R; Polarity: Non-Polarized
NT2-NT6 NT8 = D-002-0002: Net-Tie, Surface Mount, 2 x 0.4mm x 0.2mm SMT Pads - For 0.2mm Track
R1-R4 = D-100-0088: Resistor, 4K7 1% 0402 (1005); Power Rating: 63 mW; Resistance: 4.7 K
R7-R10 R12 R14 R18 R20 R22-R24 = D-100-0131: Resistor, 100R 1% 0402 (1005); Power Rating: 63 mW
U1 = D-241-0021: FPGA, Xilinx Virtex-4, XC4VSX35; Supply Voltage: mV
